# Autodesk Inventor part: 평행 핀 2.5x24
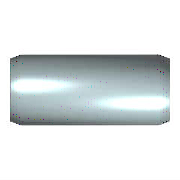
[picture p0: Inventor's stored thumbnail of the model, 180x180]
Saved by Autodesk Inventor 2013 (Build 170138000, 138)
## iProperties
IsCustomPart: 1
Created: 2012-02
Part Number: 평행 핀 2.5x24
Material: 강철, 연강
Description: 평행 핀
Document SubType Name: 판금
Standard: KS B 1320
Designer: mduedu
Standards Organization: KS
Language: ko-KR
Size Designation: B 2.5 x  24
Categories: <MemberInstance><Categories><Category DisplayName="조임쇠" InternalName="e4da775c-781d-43d5-af7c-5136215cf5a6" Mnemonic="FSTN"><Category DisplayName="핀" InternalNa
Density: 1 g/cm^3
Sheet Metal Rule: 기본값
Author: mduedu
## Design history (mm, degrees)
sketch "스케치"
  geometry: C1 r 1.25 at (0, 0); 1 further point
  constraints: 1 centre point, 1 coincident
  dimensions: "d1" = 2.5 diameter of C1 (= NND)
extrude "본체" new body sketch "스케치" distance "d2" = 24 (= NLG); taper "d3" = 0 deg
chamfer "스케치2" distance "d8" = 0.4 (= PHH); stored, may be unused: angle "d9" = 15 deg (= FAWI), second distance "d12" = 0.4 (= PHH)
node "작업 평면1"
body "Solid1"
chamfer "모따기1" distance "d4" = 0.4 (= PHH); stored, may be unused: angle "d5" = 15 deg (= FAWI), second distance "d11" = 0.4 (= PHH)
other parameters: "NND" = 2.5 [user parameter; used in 1 equation term], "NLG" = 24 [user parameter; used in 1 equation term], "PHH" = 0.4 [user parameter; used in 4 equation terms], "FAWI" = 15 deg [user parameter; used in 2 equation terms], "d13" = 0, "d15" = 0, "d16" = 0, "KAH" = 0.3 [user parameter], "K계수" = 4.4, "BendRadius" = 0.5 (derived), "BendReliefWidth" = 0.5 (derived), "BendReliefDepth" = 0.25 (derived), "CornerReliefSize" = 2 (derived), "SeamGap" = 0.01, "MinimumRemnant" = 1 (derived), "TransitionRadius" = 0.5 (= BendRadius)
